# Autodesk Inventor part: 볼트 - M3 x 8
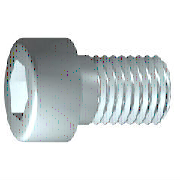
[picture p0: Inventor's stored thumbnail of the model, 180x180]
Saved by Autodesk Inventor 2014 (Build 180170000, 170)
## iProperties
IsCustomPart: 0
Created: 2012-02
Part Number: 볼트 - M3 x 8
Material: 스테인리스강
Description: 6각 소켓 머리 캡 나사
Document SubType Name: Modeling
Standard: ISO 4762
Designer: mduedu
Standard Revision: Fourth edition 2004-03-01
Standards Organization: ISO
Language: ko-KR
Size Designation: M3 x 8
Categories: <MemberInstance><Categories><Category DisplayName="조임쇠" InternalName="e4da775c-781d-43d5-af7c-5136215cf5a6" Mnemonic="FSTN"><Category DisplayName="볼트" InternalN
Density: 7.75 g/cm^3
Appearance: 반광택
Author: mduedu
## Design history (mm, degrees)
sketch "스케치1"
  geometry: L1 (-0.867, 0)-(8, 0); L2 (8, 0)-(8, 1.5); L3 (8, 1.5)-(1.25, 1.5); L4 (1.25, 1.5)-(0.943, 1.5); L5 (0.943, 1.5)-(0, 1.5); L6 (0, 1.5)-(0, 2.75); L7 (0, 2.75)-(-3, 2.75); L8 (-3, 2.75)-(-3, 1.443); L9 (-3, 1.443)-(-1.7, 1.443); L10 (-1.7, 1.443)-(-0.867, 0); L11 (-5.2, 0)-(10.2, 0) reference; L12 (0, -0.55)-(0, 3.3) reference; L13 (1.25, 1.5)-(0, 1.5)
  constraints: 22 end point, 6 parallel, 2 collinear, 2 perpendicular, 1 horizontal, 1 point on line
  dimensions: "d1" = 6.75 distance from line of L3.end L2 (= GEL); "d2" = 0.30683 distance of L4.end L3.end (computed from GAL); "d3" = 3 distance between parallel lines of L8 L6 (= KOH); "d4" = 1.3 distance of L8.end L9.end (= INTI); "d5" = 60 deg angle of L10 L1; "d6" = 3 diameter of L3 L1 (= GD); "d7" = 3 diameter of L5 L1 (= BDM); "d8" = 2.88675 diameter of L9 L1 (= 1.1547 x SW); "d9" = 5.5 diameter of L7 L1 (= KOD); "d26" = 8 distance between parallel lines of L12 L2 (= NLG)
revolve "본체" sketch "스케치1" stored, may be unused: angle "d10" = 90 deg
sketch "스케치2"
  geometry: L1 (0, -3.85)-(0, 3.85) reference; L2 (-3.85, 0)-(3.85, 0) reference; L3 (1.443, 0)-(0.722, -1.25); L4 (0.722, -1.25)-(-0.722, -1.25); L5 (-0.722, -1.25)-(-1.443, 0); L6 (-1.443, 0)-(-0.722, 1.25); L7 (-0.722, 1.25)-(0.722, 1.25); L8 (0.722, 1.25)-(1.443, 0); 2 further points
  constraints: 12 end point, 1 coincident, 1 horizontal alignment, 1 point on line, 12 other
extrude "슬롯" join sketch "스케치2" stored distance "d11" = 10; taper "d12" = 0 deg
workplane "Work Plane1"
fillet "Fillet2" dims "d30" = 0.1 (= R)
body "Solid1"
fillet "모깎기1" dims "d17" = 0.3 (= RR)
feature "스레드" dims "d13" = 6.75 (= GEL), "d14" = 0
chamfer "모따기1" distance "d15" = 0.30673 (= -0.5 x SPD + 0.5 x GD); stored, may be unused: second distance "d16" = 0.30673 (= GUL), angle "d27" = 45 deg
other parameters: "GD" = 3 [user parameter; used in 2 equation terms], "NLG" = 8 [user parameter; used in 1 equation term], "GEL" = 6.75 [user parameter; used in 2 equation terms], "KOD" = 5.5 [user parameter; used in 1 equation term], "KOH" = 3 [user parameter; used in 1 equation term], "INTI" = 1.3 [user parameter; used in 1 equation term], "GAL" = 0.30673 (= 0.61345 x PTC) [user parameter; used in 1 equation term], "GUL" = 0.30673 (= 0.61345 x PTC) [user parameter; used in 1 equation term], "BDM" = 3 (= NND) [user parameter; used in 1 equation term], "SW" = 2.5 [user parameter; used in 2 equation terms], "RR" = 0.3 [user parameter; used in 1 equation term], "SPD" = 2.38655 (= NND - 1.2269 x PTC) [user parameter; used in 1 equation term], "d19" = 0, "d28" = 0, "d29" = 0, "R" = 0.1 [user parameter; used in 1 equation term], "TOA" = 30 deg [user parameter], "GD1" = 2.38655 (= THREADDIA - 1.2269 x PTC) [user parameter], "THREADDIA" = 3 [user parameter; used in 1 equation term], "FAWI" = 45 deg [user parameter], "PTC" = 0.5 [user parameter; used in 5 equation terms], "NND" = 3 [user parameter; used in 2 equation terms], "E0" = 2.8875 (= 1.155 x SW) [user parameter]
